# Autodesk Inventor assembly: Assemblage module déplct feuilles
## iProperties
Created: 2011-02
Part Number: Assemblage module déplct feuilles
Document SubType Name: Assembly
Designer: eric
Norme de conversion: IGES 5.3
Nom du fichier: No Iges File Name specified
Préprocesseur: Autodesk Inventor 2011
Postprocesseur: Build: 342, Release: 2008 SP3 - Date: Tue 05/27/2008
Unités envoyées: MM
Incertitude: 0.01
Author: eric
